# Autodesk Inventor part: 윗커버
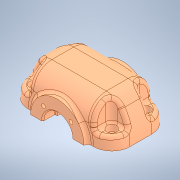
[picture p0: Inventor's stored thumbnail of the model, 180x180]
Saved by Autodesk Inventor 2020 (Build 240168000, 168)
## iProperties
Created: 2024-05
Part Number: 윗커버
Material: 알루미늄 6061
Document SubType Name: Modeling
Designer: oem
Density: 2.7 g/cm^3
Appearance: 기본값
Author: jhkim
Sending System: Autodesk Inventor 2025
Preprocessor: ST-DEVELOPER v20
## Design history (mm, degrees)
feature "솔리드1"
node "솔리드2"
